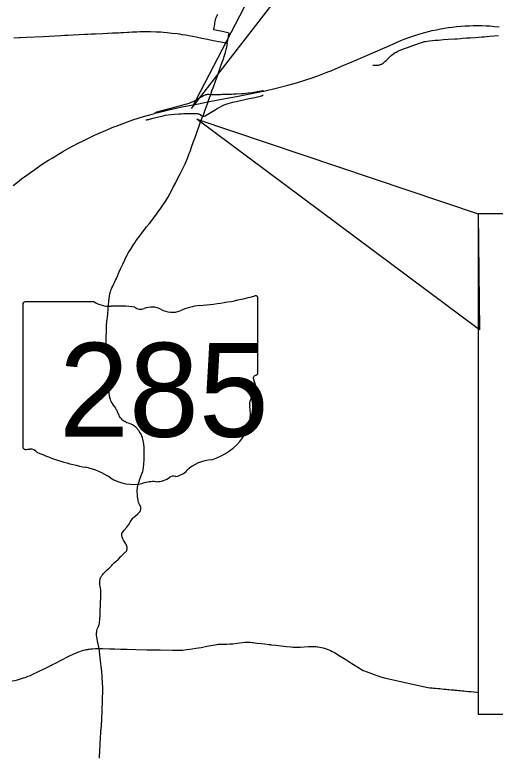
# Model space of a CAD drawing. Extents: x 1761803 to 2441803, y 509895 to 949895.
# Drawn here: x 2257532 to 2271766, y 817939 to 839765 of the extents above; entities that cross this region are included whole.
import ezdxf

# ---------------------------------------------------------------- set-up
doc = ezdxf.new("R2010")
doc.units = 0
for name, color, linetype in [('GM_X_County_Road', 7, 'Continuous'), ('GM_X_Minor_Lake', 7, 'Continuous'), ('GM_X_Minor_River', 7, 'Continuous'), ('GM_X_Minor_River_Text', 7, 'Continuous'), ('GM_X_State_Location', 7, 'Continuous'), ('GM_X_Township_Road', 7, 'Continuous'), ('GM_X_US_Location', 7, 'Continuous')]:
    doc.layers.add(name, color=color, linetype=linetype)

msp = doc.modelspace()

# ---------------------------------------------------------------- linework, layer by layer
at = {"layer": 'GM_X_County_Road'}
msp.add_lwpolyline([(2268140, 838271), (2268148, 838271), (2268210, 838271), (2268263, 838271), (2268295, 838274), (2268324, 838278), (2268349, 838284), (2268370, 838291), (2268394, 838301), (2268417, 838313), (2268444, 838331), (2268470, 838350), (2268500, 838375), (2268534, 838406), (2268638, 838510), (2268686, 838555), (2268724, 838587), (2268764, 838617), (2268799, 838641), (2268830, 838659), (2268865, 838678), (2268901, 838695), (2268950, 838715), (2269076, 838761), (2269162, 838794), (2269248, 838826), (2269325, 838855), (2269414, 838887), (2269495, 838914), (2269554, 838934), (2269619, 838955), (2269664, 838968), (2269699, 838975), (2269745, 838983), (2269817, 838992), (2269905, 839001), (2269990, 839008), (2270085, 839014), (2270232, 839027), (2270376, 839036), (2270569, 839049), (2270641, 839054), (2270733, 839062), (2270791, 839067), (2270915, 839076), (2271023, 839084), (2271173, 839093), (2271278, 839102), (2271373, 839108), (2271435, 839113), (2271494, 839117), (2271592, 839126), (2271735, 839138), (2271866, 839149)], dxfattribs=at)
at = {"layer": 'GM_X_Minor_Lake'}
for points in [[(2263428, 839315), (2263439, 839389), (2263445, 839429), (2263456, 839487), (2263464, 839527), (2263470, 839563), (2263481, 839615), (2263491, 839656), (2263498, 839678), (2263508, 839703), (2263519, 839724), (2263532, 839743), (2263553, 839769)], [(2263885, 839221), (2263801, 839239), (2263730, 839254), (2263624, 839275), (2263515, 839297), (2263428, 839315)], [(2263825, 838920), (2263842, 839002), (2263844, 839011), (2263860, 839093), (2263864, 839109), (2263868, 839131), (2263885, 839221)], [(2260627, 832143), (2260666, 832230), (2260733, 832376), (2260793, 832504), (2260824, 832568), (2260864, 832644), (2260904, 832715), (2260968, 832822), (2261040, 832936), (2261085, 833004), (2261133, 833071), (2261237, 833214), (2261296, 833292), (2261439, 833476), (2261521, 833583), (2261678, 833789), (2261781, 833925), (2261859, 834031), (2261942, 834149), (2261978, 834204), (2262010, 834254), (2262067, 834350), (2262126, 834456), (2262175, 834549), (2262230, 834657), (2262291, 834773), (2262356, 834902), (2262429, 835046), (2262540, 835265), (2262579, 835345), (2262613, 835419), (2262642, 835489), (2262671, 835563), (2262704, 835655), (2262725, 835711), (2262736, 835741), (2262770, 835837), (2262830, 836011), (2262885, 836158), (2262915, 836249), (2262934, 836301), (2262977, 836414), (2263026, 836561), (2263101, 836756)], [(2260076, 822353), (2260076, 822363), (2260081, 822454), (2260085, 822572), (2260086, 822638), (2260084, 822687), (2260080, 822736), (2260075, 822772), (2260066, 822824), (2260056, 822882), (2260051, 822920), (2260049, 822962), (2260053, 822990), (2260055, 823009), (2260059, 823028), (2260066, 823053), (2260072, 823075), (2260079, 823092), (2260083, 823101), (2260090, 823114), (2260094, 823120), (2260100, 823131), (2260108, 823145), (2260128, 823170), (2260151, 823198), (2260154, 823201), (2260169, 823216), (2260182, 823230), (2260196, 823243), (2260232, 823277), (2260251, 823295), (2260271, 823312), (2260330, 823368), (2260356, 823393), (2260384, 823421), (2260409, 823447), (2260432, 823470), (2260492, 823530), (2260530, 823566), (2260604, 823636), (2260677, 823709), (2260737, 823769), (2260777, 823807), (2260806, 823834), (2260822, 823851), (2260838, 823872), (2260848, 823890), (2260855, 823906), (2260860, 823925), (2260862, 823939), (2260863, 823962), (2260859, 823989), (2260853, 824012), (2260846, 824031), (2260838, 824049), (2260821, 824081), (2260786, 824140), (2260753, 824197), (2260735, 824233), (2260722, 824264), (2260712, 824292), (2260706, 824316), (2260702, 824340), (2260705, 824374), (2260709, 824388), (2260722, 824417), (2260733, 824436), (2260751, 824464), (2260773, 824492), (2260850, 824580), (2260881, 824619), (2260907, 824657), (2260951, 824730), (2260980, 824777), (2261009, 824816), (2261033, 824842), (2261053, 824862), (2261103, 824909), (2261176, 824975), (2261212, 825009), (2261227, 825027), (2261243, 825048), (2261256, 825072), (2261261, 825084), (2261267, 825107), (2261268, 825117), (2261269, 825148), (2261264, 825177), (2261261, 825187), (2261245, 825224), (2261228, 825256), (2261213, 825288), (2261201, 825325), (2261193, 825357), (2261187, 825388), (2261178, 825440), (2261172, 825492), (2261168, 825528), (2261164, 825566), (2261161, 825605), (2261159, 825651), (2261160, 825687), (2261165, 825732), (2261171, 825771), (2261179, 825809), (2261188, 825847), (2261199, 825885), (2261216, 825937), (2261239, 825999), (2261267, 826076), (2261298, 826159), (2261323, 826231), (2261339, 826291), (2261345, 826335), (2261351, 826375), (2261356, 826429), (2261365, 826609), (2261370, 826763), (2261370, 826883), (2261363, 826964), (2261344, 827096), (2261326, 827190), (2261312, 827242), (2261297, 827278), (2261283, 827312), (2261267, 827345), (2261249, 827376), (2261231, 827404), (2261224, 827415), (2261206, 827438), (2261197, 827451), (2261187, 827463), (2261179, 827473), (2261164, 827490), (2261135, 827522), (2261106, 827549), (2261078, 827573), (2261052, 827592), (2261018, 827613), (2260985, 827628), (2260954, 827640), (2260898, 827659), (2260853, 827676), (2260820, 827690), (2260789, 827707), (2260762, 827724), (2260733, 827745), (2260711, 827764), (2260691, 827785), (2260672, 827807), (2260656, 827831), (2260640, 827859), (2260623, 827894), (2260588, 827971), (2260581, 827987), (2260575, 828001), (2260565, 828025), (2260553, 828048), (2260540, 828071), (2260522, 828102), (2260495, 828142), (2260457, 828195), (2260426, 828240), (2260406, 828273), (2260391, 828301), (2260379, 828328), (2260368, 828358), (2260359, 828393), (2260350, 828428), (2260342, 828460), (2260336, 828493), (2260332, 828537), (2260335, 828637), (2260337, 828724), (2260341, 828813), (2260345, 828865), (2260347, 828890), (2260350, 828916), (2260356, 828954), (2260363, 828985), (2260365, 828991), (2260379, 829042), (2260388, 829073), (2260390, 829082), (2260399, 829109), (2260403, 829124), (2260409, 829142), (2260414, 829161), (2260420, 829178), (2260424, 829191), (2260427, 829200), (2260430, 829209), (2260434, 829224), (2260444, 829266), (2260450, 829299), (2260451, 829319), (2260451, 829339), (2260450, 829349), (2260446, 829372), (2260439, 829397), (2260431, 829419), (2260417, 829453), (2260393, 829500), (2260368, 829542), (2260350, 829573), (2260331, 829611), (2260324, 829629), (2260313, 829656), (2260306, 829674), (2260304, 829682), (2260301, 829690), (2260290, 829724), (2260285, 829742), (2260282, 829752), (2260268, 829802), (2260261, 829834), (2260255, 829869), (2260250, 829914), (2260245, 829983), (2260243, 830042), (2260242, 830065), (2260242, 830071), (2260242, 830097), (2260242, 830123), (2260243, 830195), (2260245, 830245), (2260248, 830359), (2260255, 830543), (2260263, 830670), (2260264, 830683), (2260265, 830699), (2260268, 830722), (2260269, 830732), (2260276, 830797), (2260287, 830905), (2260302, 831042), (2260312, 831156), (2260324, 831273), (2260334, 831364), (2260341, 831413), (2260344, 831442), (2260350, 831481), (2260355, 831509), (2260355, 831510), (2260362, 831542), (2260374, 831583), (2260388, 831626), (2260406, 831668), (2260433, 831724), (2260466, 831787), (2260489, 831831), (2260521, 831896), (2260546, 831953), (2260582, 832037), (2260600, 832080), (2260627, 832143), (2260627, 832143)], [(2260029, 820981), (2259983, 821204), (2259972, 821262), (2259960, 821330), (2259955, 821372), (2259953, 821410), (2259955, 821446), (2259960, 821481), (2259968, 821519), (2259978, 821554), (2259984, 821572), (2260003, 821621), (2260019, 821664), (2260030, 821699), (2260038, 821731), (2260045, 821773), (2260051, 821816), (2260056, 821872), (2260059, 821944), (2260060, 821973), (2260062, 822022), (2260063, 822072), (2260066, 822167), (2260068, 822216), (2260072, 822294), (2260075, 822337), (2260075, 822343), (2260076, 822353)], [(2260029, 820981), (2260128, 820980), (2260134, 820980), (2260347, 820976), (2260501, 820971), (2260675, 820969), (2260859, 820964), (2261115, 820957), (2261453, 820949), (2261738, 820942), (2261840, 820940), (2262207, 820931), (2262338, 820930), (2262410, 820932), (2262461, 820934), (2262516, 820938), (2262623, 820951), (2262789, 820975), (2262899, 820992), (2263058, 821018), (2263226, 821051), (2263403, 821087), (2263465, 821097), (2263512, 821105), (2263561, 821109), (2263598, 821112), (2263731, 821113), (2263816, 821115), (2263901, 821118), (2263950, 821122), (2263996, 821127), (2264058, 821136), (2264194, 821155), (2264282, 821166), (2264344, 821172), (2264393, 821173), (2264451, 821172), (2264507, 821169), (2264561, 821164)], [(2264561, 821164), (2264598, 821160), (2264715, 821146), (2264839, 821131), (2264940, 821119), (2265048, 821106), (2265111, 821099), (2265129, 821097), (2265259, 821082), (2265344, 821072), (2265429, 821062), (2265579, 821045), (2265706, 821031), (2265784, 821024), (2265843, 821020), (2265883, 821019), (2265929, 821020), (2265988, 821022), (2266237, 821043), (2266295, 821046), (2266351, 821046), (2266403, 821044), (2266455, 821040), (2266495, 821035), (2266507, 821033), (2266568, 821022), (2266619, 821012), (2266670, 821000), (2266726, 820983), (2266784, 820964), (2266836, 820943), (2266885, 820922), (2266937, 820895), (2267001, 820861), (2267083, 820813), (2267125, 820788), (2267217, 820731), (2267336, 820657), (2267516, 820543), (2267741, 820403), (2267806, 820364), (2267855, 820337), (2267890, 820320), (2267941, 820299), (2268022, 820269), (2268099, 820241), (2268182, 820210), (2268290, 820172), (2268374, 820144), (2268474, 820111), (2269771, 819828)], [(2258650, 820508), (2258738, 820553), (2258926, 820646), (2259119, 820743), (2259278, 820822), (2259338, 820849), (2259402, 820876), (2259464, 820899), (2259514, 820916), (2259571, 820932), (2259632, 820947), (2259661, 820953), (2259690, 820959), (2259714, 820963), (2259738, 820967), (2259784, 820972), (2259840, 820977), (2259926, 820980), (2260029, 820981)], [(2260105, 820372), (2260094, 820460), (2260073, 820622), (2260052, 820794), (2260038, 820901), (2260029, 820981)], [(2258364, 820365), (2258439, 820402), (2258625, 820495), (2258650, 820508)], [(2257458, 820022), (2257537, 820040), (2257617, 820060), (2257705, 820085), (2257793, 820112), (2257870, 820139), (2257934, 820163), (2257995, 820188), (2258069, 820222), (2258238, 820303), (2258338, 820352), (2258364, 820365)], [(2260137, 819780), (2260137, 819794), (2260130, 820000), (2260126, 820089), (2260122, 820171), (2260114, 820288), (2260110, 820327), (2260105, 820372)], [(2269771, 819828), (2269832, 819823), (2269896, 819816), (2269938, 819813), (2270000, 819807), (2270072, 819800), (2270129, 819794), (2270187, 819789), (2270246, 819783), (2270314, 819776), (2270366, 819771), (2270389, 819769), (2270464, 819762), (2270510, 819757), (2270536, 819755), (2270568, 819752), (2270604, 819748), (2270637, 819746), (2270679, 819742), (2270738, 819736), (2270787, 819732), (2270833, 819728), (2270882, 819723), (2270973, 819713), (2271009, 819709), (2271055, 819705), (2271136, 819697), (2271208, 819689), (2271257, 819684)], [(2260107, 818783), (2260109, 818815), (2260113, 818890), (2260116, 818972), (2260119, 819047), (2260121, 819100), (2260123, 819175), (2260125, 819267), (2260127, 819325), (2260127, 819331), (2260130, 819414), (2260136, 819604), (2260137, 819624), (2260138, 819696), (2260138, 819717), (2260137, 819780)], [(2260039, 817734), (2260040, 817755), (2260043, 817801), (2260045, 817849), (2260048, 817887), (2260050, 817926), (2260052, 817970), (2260055, 818017), (2260058, 818074), (2260062, 818136), (2260062, 818142), (2260066, 818214), (2260070, 818289), (2260075, 818364), (2260081, 818466), (2260087, 818555), (2260090, 818586), (2260093, 818614), (2260094, 818623), (2260099, 818672), (2260103, 818708), (2260106, 818753), (2260107, 818783)]]:
    msp.add_lwpolyline(points, dxfattribs=at)
at = {"layer": 'GM_X_Minor_River'}
msp.add_lwpolyline([(2257487, 834703), (2257610, 834801), (2257737, 834900), (2257861, 834992), (2258001, 835094), (2258125, 835181), (2258274, 835283), (2258407, 835372), (2258534, 835454), (2258637, 835518), (2258828, 835634), (2258977, 835722), (2259111, 835797), (2259264, 835881), (2259409, 835957), (2259558, 836032), (2259753, 836127), (2259892, 836193), (2260032, 836257), (2260222, 836338), (2260398, 836411), (2260467, 836439), (2260469, 836439), (2260535, 836465), (2260710, 836531), (2260876, 836591), (2261034, 836646), (2261190, 836697), (2261350, 836747), (2261535, 836802), (2261671, 836840), (2261680, 836843), (2261858, 836889), (2262020, 836930), (2262097, 836947), (2262315, 836993), (2262485, 837031), (2262974, 837123), (2263199, 837170), (2263252, 837180), (2263510, 837230), (2263762, 837280), (2264098, 837344), (2264346, 837392), (2264595, 837441), (2264839, 837489), (2264910, 837502), (2265315, 837594), (2265623, 837674), (2265810, 837726), (2266036, 837793), (2266155, 837831), (2266314, 837885), (2266506, 837953), (2266660, 838010), (2266761, 838048), (2266837, 838078), (2266892, 838100), (2266903, 838104), (2266962, 838128), (2267014, 838150), (2267216, 838236), (2267501, 838358), (2267915, 838540), (2268213, 838669), (2268507, 838798), (2268817, 838932), (2268971, 838997), (2269069, 839036), (2269176, 839077), (2269321, 839129), (2269445, 839170), (2269568, 839208), (2269684, 839241), (2269789, 839268), (2269901, 839295), (2270022, 839321), (2270144, 839345), (2270261, 839366), (2270374, 839383), (2270491, 839399), (2270618, 839413), (2270742, 839424), (2270879, 839434), (2271007, 839440), (2271109, 839442), (2271237, 839443), (2271364, 839442), (2271495, 839438), (2271613, 839431), (2271744, 839420), (2271884, 839405)], dxfattribs=at)
at = {"layer": 'GM_X_Minor_River_Text'}
for points in [[(2257506, 839082), (2257663, 839090), (2257679, 839090), (2257883, 839100), (2258124, 839112), (2258373, 839124), (2258553, 839133), (2258718, 839142), (2258893, 839149), (2259013, 839155), (2259051, 839157), (2259103, 839159), (2259264, 839168), (2259432, 839176), (2259594, 839184), (2259700, 839189), (2259799, 839195), (2259806, 839195), (2259924, 839201), (2260146, 839212), (2260278, 839219)], [(2260278, 839219), (2260290, 839219), (2260426, 839224), (2260537, 839229), (2260605, 839233)], [(2260605, 839233), (2260678, 839238), (2260749, 839242), (2260870, 839248), (2260910, 839250)], [(2260910, 839250), (2261014, 839254), (2261149, 839260), (2261240, 839264), (2261358, 839266), (2261476, 839267), (2261555, 839266), (2261719, 839261), (2261860, 839254), (2261941, 839249), (2262043, 839240), (2262118, 839233), (2262196, 839223), (2262339, 839204), (2262410, 839194), (2262483, 839183)], [(2262483, 839183), (2262604, 839164), (2262691, 839148), (2262907, 839105), (2263077, 839070), (2263241, 839038), (2263412, 839004), (2263640, 838957), (2263787, 838928), (2263825, 838920)], [(2263825, 838920), (2263801, 838799), (2263784, 838720), (2263779, 838702), (2263763, 838639), (2263728, 838520), (2263696, 838420), (2263670, 838349), (2263631, 838238), (2263577, 838090), (2263524, 837946), (2263469, 837788), (2263399, 837590)], [(2263825, 838920), (2263801, 838799), (2263784, 838720), (2263779, 838702), (2263763, 838639), (2263728, 838520), (2263696, 838420), (2263670, 838349), (2263631, 838238), (2263577, 838090), (2263524, 837946), (2263469, 837788), (2263399, 837590)], [(2263399, 837590), (2263364, 837495), (2263328, 837393), (2263273, 837239), (2263262, 837209)], [(2263399, 837590), (2263364, 837495), (2263328, 837393), (2263273, 837239), (2263262, 837209)], [(2263472, 836948), (2263529, 836982), (2263612, 837029), (2263676, 837062), (2263736, 837090), (2263797, 837114), (2263859, 837136), (2263924, 837156), (2263997, 837176), (2264087, 837197), (2264479, 837280), (2264642, 837316), (2264840, 837363), (2264861, 837369), (2264877, 837376), (2264884, 837381), (2264891, 837389)], [(2263472, 836948), (2263529, 836982), (2263612, 837029), (2263676, 837062), (2263736, 837090), (2263797, 837114), (2263859, 837136), (2263924, 837156), (2263997, 837176), (2264087, 837197), (2264479, 837280), (2264642, 837316), (2264840, 837363), (2264861, 837369), (2264877, 837376), (2264884, 837381), (2264891, 837389)], [(2263262, 837209), (2263252, 837180), (2263229, 837112), (2263218, 837082), (2263211, 837061), (2263194, 837014), (2263183, 836983), (2263147, 836881), (2263101, 836756)], [(2263262, 837209), (2263252, 837180), (2263229, 837112), (2263218, 837082), (2263211, 837061), (2263194, 837014), (2263183, 836983), (2263147, 836881), (2263101, 836756)], [(2263101, 836756), (2263116, 836755), (2263130, 836756), (2263143, 836759), (2263158, 836763), (2263174, 836770), (2263256, 836819), (2263355, 836878), (2263472, 836948)], [(2263101, 836756), (2263116, 836755), (2263130, 836756), (2263143, 836759), (2263158, 836763), (2263174, 836770), (2263256, 836819), (2263355, 836878), (2263472, 836948)]]:
    msp.add_lwpolyline(points, dxfattribs=at)
at = {"layer": 'GM_X_State_Location'}
for points in [[(2262773, 836988), (2271645, 848451), (2268723, 848457)], [(2262930, 836670), (2271257, 833868), (2271299, 830427)], [(2271257, 819034), (2300661, 819034), (2300661, 833868), (2271257, 833868)]]:
    msp.add_lwpolyline(points, close=True, dxfattribs=at)
at = {"layer": 'GM_X_Township_Road'}
for p, q in [((2264735, 829152), (2264735, 831363)), ((2257774, 831186), (2257774, 826959)), ((2259881, 831258), (2257843, 831258)), ((2264734, 829153), (2264735, 829152))]:
    msp.add_line(p, q, dxfattribs=at)
for centre, major_axis, start_param, end_param in [((2262255, 837021), (7382, 0), 4.814394, 5.042369), ((2264658, 831372), (77.5, 0), 6.141152, 7.989035), ((2257854, 831195), (80.6, 0), 1.712693, 3.28349), ((2260367, 831749), (782, 0), 4.042523, 4.731795), ((2260626, 828886), (2808, 0), 1.404758, 1.657858), ((2263197, 829968), (1485, 0), 1.699011, 2.107814), ((2261263, 831217), (226, 0), 3.836095, 5.185415), ((2261595, 830728), (469, 0), 0.950623, 2.079405), ((2262200, 831398), (564, 0), 4.081561, 5.145723), ((2264717, 828990), (120, 0), 1.883978, 3.671073), ((2264652, 829144), (82.9, 0), 5.05454, 6.418171), ((2263954, 828710), (720, 0), 5.934695, 6.695948), ((2265012, 828227), (524, 0), 2.387724, 3.262537), ((2262669, 827946), (1846, 0), 5.101752, 6.440018), ((2257855, 826950), (81.4, 0), 3.00124, 4.508301), ((2257867, 827382), (621, 0), 4.665946, 4.897461), ((2257994, 826715), (224, 0), 0.519207, 1.627899), ((2260820, 830513), (5331, 0), 4.195997, 4.488961), ((2263447, 825773), (1011, 0), 1.647645, 2.488434), ((2259231, 825060), (1668, 0), 0.823519, 1.323587), ((2262166, 826550), (597, 0), 4.937069, 5.64225), ((2261035, 826694), (1058, 0), 4.026481, 4.996735), ((2261646, 825233), (870, 0), 1.495662, 1.94098), ((2261724, 826378), (564, 0), 4.691044, 5.507374), ((2262234, 825969), (159, 0), 1.147584, 2.315152)]:
    msp.add_ellipse(centre, major_axis=major_axis, ratio=0.8, start_param=start_param, end_param=end_param, dxfattribs=at)
at = {"layer": 'GM_X_US_Location'}
for points in [[(2264910, 837502), (2264896, 837504), (2264873, 837506), (2264858, 837505), (2264838, 837503), (2264767, 837490), (2264564, 837455), (2264447, 837436), (2264376, 837427), (2264307, 837420), (2264252, 837416), (2264098, 837409), (2264016, 837406), (2263954, 837404), (2263914, 837402), (2263898, 837402), (2263846, 837401), (2263787, 837399), (2263731, 837398), (2263669, 837396), (2263629, 837395), (2263580, 837394), (2263541, 837392), (2263476, 837391), (2263374, 837392), (2263328, 837393)], [(2263328, 837393), (2263281, 837396), (2263244, 837397), (2263229, 837397), (2263212, 837395), (2263197, 837393), (2263172, 837385), (2263148, 837375), (2263124, 837364), (2263093, 837346), (2263034, 837310), (2262935, 837253), (2262865, 837216), (2262803, 837185), (2262747, 837160), (2262686, 837136), (2262620, 837114), (2262542, 837091), (2262405, 837054), (2262151, 836989), (2261961, 836938), (2261767, 836884), (2261748, 836878), (2261734, 836873), (2261718, 836865), (2261697, 836854), (2261679, 836844), (2261671, 836840)], [(2261416, 836652), (2261444, 836655), (2261461, 836656), (2261484, 836658), (2261509, 836663), (2261525, 836667), (2261636, 836698), (2261756, 836731), (2261845, 836753), (2261929, 836771), (2262000, 836784), (2262074, 836795), (2262169, 836807), (2262260, 836816), (2262394, 836828), (2262466, 836832), (2262529, 836835), (2262630, 836837), (2262745, 836839), (2262860, 836840), (2262906, 836838), (2262938, 836835), (2262961, 836831), (2262986, 836823), (2263004, 836815), (2263021, 836805), (2263062, 836777), (2263075, 836768), (2263089, 836760), (2263101, 836756)]]:
    msp.add_lwpolyline(points, dxfattribs=at)

# ---------------------------------------------------------------- texts
at = {"layer": 'GM_X_Township_Road'}
msp.add_text('285', height=2784.4, dxfattribs=at).set_placement((2258845, 827257))

doc.saveas('drawing.dxf')
